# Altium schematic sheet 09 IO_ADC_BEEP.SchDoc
size 246 x 182 mm
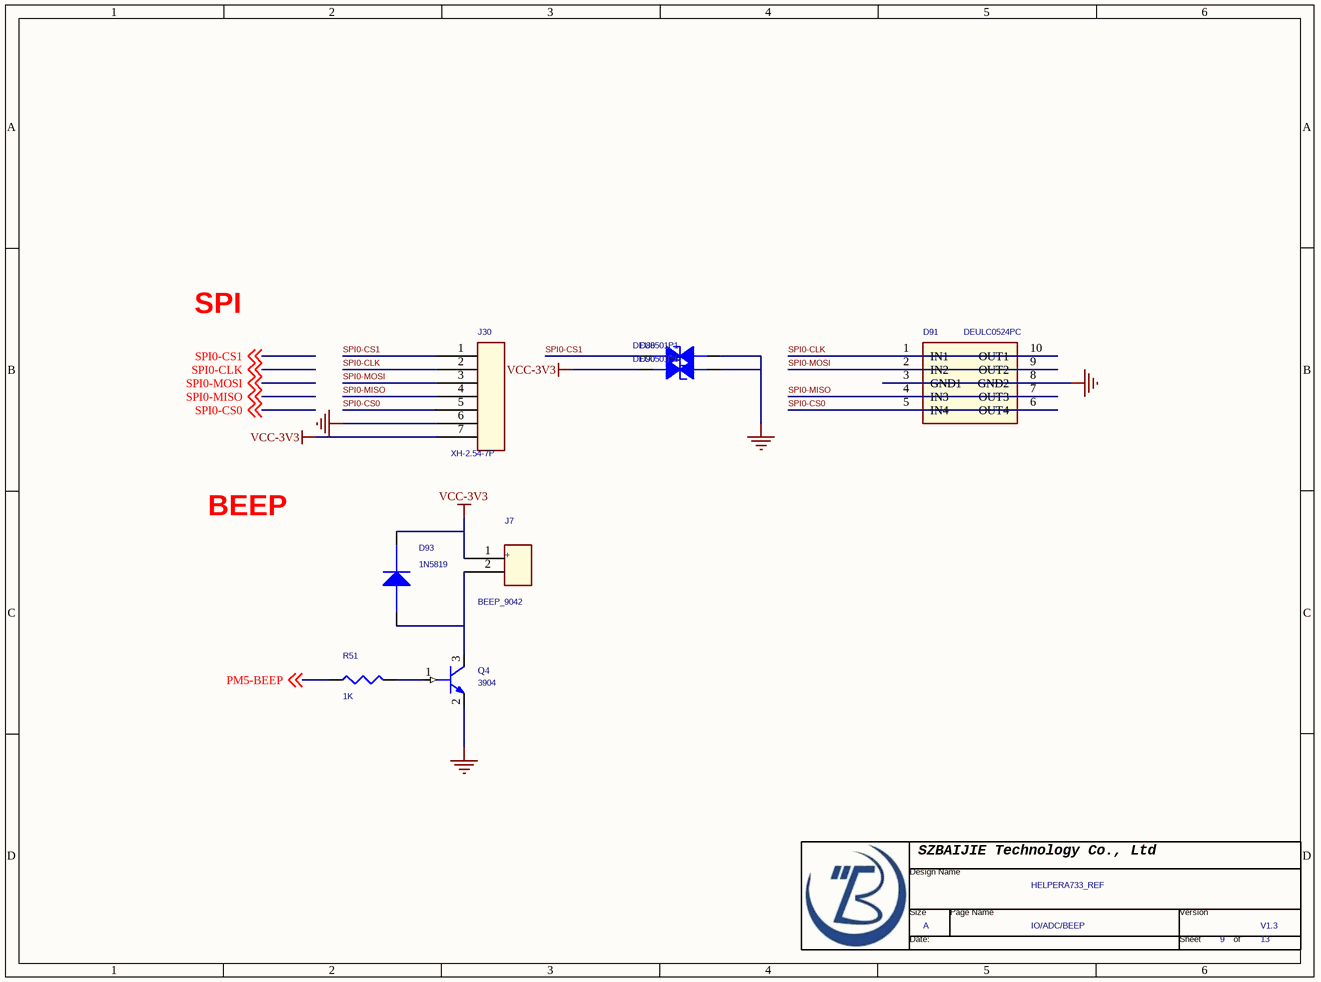
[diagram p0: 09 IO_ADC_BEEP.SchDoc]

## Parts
*  Page Count: 13  Page Number: 9  Page Size: A  Title: HELPERA733_REF  RevCode: V1.3  Doc: IO/ADC/BEEP  (hidden comment: TitleBlock0-BJ)  (graphical)
D88  DEU0501P1  [ESD0402]
D90  DEU0501P1  [ESD0402]
D91  DEULC0524PC  [RCLAMP0524P]
D93  1N5819  [SOD323]
J7  BEEP_9042  [BEEP_9042]
J30  XH-2.54-7P  [XH-2.54-7P]
Q4  3904  [SOT23]
R51  1K  [R0402]

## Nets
GND: D88.2(CATHODE) D90.2(CATHODE) D91.3(GND1) D91.8(GND2) J30.6 Q4.2(EMITTER)
VCC-3V3: D90.1(ANODE) D93.2(CATHODE) J7.1 J30.7
PM5-BEEP: R51.1 ; off-sheet PM5-BEEP
SPI0-CLK: D91.1(IN1) D91.10(OUT1) J30.2 ; off-sheet SPI0-CLK
SPI0-CS0: D91.5(IN4) D91.6(OUT4) J30.5 ; off-sheet SPI0-CS0
SPI0-CS1: D88.1(ANODE) J30.1 ; off-sheet SPI0-CS1
SPI0-MISO: D91.4(IN3) D91.7(OUT3) J30.4 ; off-sheet SPI0-MISO
SPI0-MOSI: D91.2(IN2) D91.9(OUT2) J30.3 ; off-sheet SPI0-MOSI
NetD93_1: D93.1(ANODE) J7.2 Q4.3(COLLECTOR)
NetQ4_1: Q4.1(BASE) R51.2

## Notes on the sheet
- SPI
- BEEP

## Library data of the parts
D88 D90 = 1_1.5KE100A_Dup1: 1ST PART DESCRIPTION: WILL ESD9B5V Bidirection ESD Protection
D91 = rRClamp0524P
D93 = BAS21/SOT_1
J7 = CON2_0_Dup1
J30 = CON4_2
Q4 = 2N3904_0
R51 = R_Dup3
